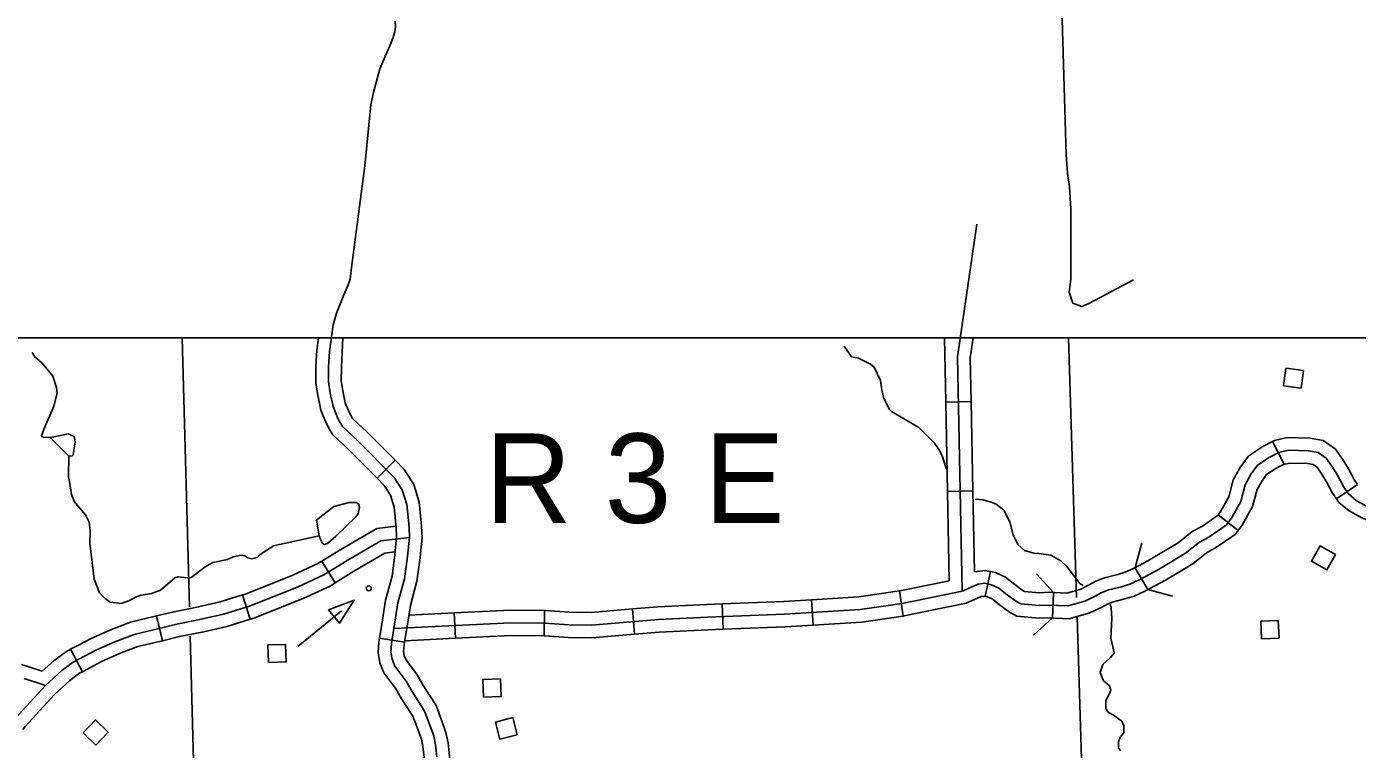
# Model space of a CAD drawing. Extents: x 1671357 to 13005564, y 567358 to 14261451.
# Drawn here: x 12758295.81 to 12758310.69, y 14259908.23 to 14259916.31 of the extents above; entities that cross this region are included whole.
import ezdxf

# ---------------------------------------------------------------- set-up
doc = ezdxf.new("R2010")
doc.units = 0
for name, color, linetype in [('2', 7, 'Continuous'), ('31', 7, 'Continuous'), ('32', 7, 'Continuous'), ('35', 7, 'Continuous'), ('38', 7, 'Continuous'), ('5', 7, 'Continuous'), ('56', 7, 'Continuous'), ('60', 7, 'Continuous')]:
    doc.layers.add(name, color=color, linetype=linetype)

msp = doc.modelspace()

# ---------------------------------------------------------------- linework, layer by layer
at = {"layer": '2'}
msp.add_line((12758241.044, 14259912.829), (12758347.654, 14259912.829), dxfattribs=at)
at = {"layer": '31'}
for p, q in [((12758299.932, 14259911.459), (12758299.731, 14259911.259)), ((12758299.758, 14259909.471), (12758300.038, 14259909.427))]:
    msp.add_line(p, q, dxfattribs=at)
for points in [[(12758299.933, 14259916.369), (12758299.936, 14259916.308), (12758299.93, 14259916.255), (12758299.911, 14259916.187), (12758299.882, 14259916.112), (12758299.762, 14259915.838), (12758299.692, 14259915.571), (12758299.661, 14259915.433), (12758299.595, 14259914.752), (12758299.44, 14259913.584), (12758299.429, 14259913.485), (12758299.408, 14259913.421), (12758299.352, 14259913.292), (12758299.277, 14259913.105), (12758299.24, 14259912.974), (12758299.199, 14259912.674), (12758299.19, 14259912.506), (12758299.188, 14259912.337), (12758299.208, 14259912.21), (12758299.239, 14259912.061), (12758299.293, 14259911.928), (12758299.344, 14259911.838), (12758299.516, 14259911.677), (12758299.923, 14259911.267), (12758299.963, 14259911.205), (12758300.011, 14259911.129), (12758300.062, 14259910.963), (12758300.088, 14259910.713), (12758300.092, 14259910.597), (12758300.071, 14259910.383), (12758300.038, 14259910.135), (12758299.963, 14259909.866)], [(12758299.086, 14259912.099), (12758299.068, 14259912.184), (12758299.046, 14259912.327), (12758299.048, 14259912.511), (12758299.058, 14259912.687), (12758299.077, 14259912.829)], [(12758299.35, 14259912.829), (12758299.332, 14259912.501), (12758299.33, 14259912.347), (12758299.347, 14259912.236), (12758299.364, 14259912.158)], [(12758299.731, 14259911.259), (12758299.417, 14259911.575), (12758299.231, 14259911.749), (12758299.165, 14259911.866), (12758299.103, 14259912.019), (12758299.086, 14259912.099)], [(12758299.364, 14259912.158), (12758299.376, 14259912.103), (12758299.421, 14259911.989), (12758299.457, 14259911.927), (12758299.615, 14259911.779), (12758299.932, 14259911.459)], [(12758299.932, 14259911.459), (12758300.034, 14259911.356), (12758300.082, 14259911.282), (12758300.141, 14259911.189), (12758300.202, 14259910.992), (12758300.229, 14259910.723), (12758300.234, 14259910.593), (12758300.217, 14259910.418)], [(12758299.731, 14259911.259), (12758299.811, 14259911.177), (12758299.843, 14259911.129), (12758299.88, 14259911.069), (12758299.922, 14259910.935), (12758299.946, 14259910.703), (12758299.949, 14259910.602), (12758299.934, 14259910.446)], [(12758299.934, 14259910.446), (12758299.929, 14259910.4), (12758299.898, 14259910.163), (12758299.824, 14259909.896), (12758299.779, 14259909.601), (12758299.758, 14259909.471)], [(12758300.217, 14259910.418), (12758300.212, 14259910.367), (12758300.177, 14259910.107), (12758300.103, 14259909.836), (12758300.059, 14259909.557), (12758300.038, 14259909.427)], [(12758299.963, 14259909.866), (12758299.919, 14259909.579), (12758299.892, 14259909.41), (12758299.885, 14259909.315), (12758299.898, 14259909.234), (12758299.931, 14259909.155), (12758299.988, 14259909.08), (12758300.056, 14259908.989), (12758300.125, 14259908.865), (12758300.259, 14259908.661), (12758300.287, 14259908.587), (12758300.321, 14259908.497), (12758300.364, 14259908.377), (12758300.383, 14259908.279), (12758300.399, 14259908.143)], [(12758300.163, 14259908.513), (12758300.154, 14259908.537), (12758300.132, 14259908.597), (12758300.004, 14259908.791), (12758299.937, 14259908.911), (12758299.874, 14259908.994), (12758299.807, 14259909.084), (12758299.76, 14259909.194), (12758299.742, 14259909.309), (12758299.751, 14259909.427), (12758299.758, 14259909.471)], [(12758300.038, 14259909.427), (12758300.033, 14259909.394), (12758300.028, 14259909.321), (12758300.035, 14259909.273), (12758300.055, 14259909.227), (12758300.101, 14259909.165), (12758300.175, 14259909.067), (12758300.247, 14259908.939), (12758300.387, 14259908.726), (12758300.42, 14259908.637), (12758300.428, 14259908.614)], [(12758300.23, 14259907.591), (12758300.247, 14259907.801), (12758300.256, 14259907.942), (12758300.257, 14259908.135), (12758300.243, 14259908.257), (12758300.227, 14259908.339), (12758300.188, 14259908.448), (12758300.163, 14259908.513)], [(12758300.428, 14259908.614), (12758300.454, 14259908.546), (12758300.501, 14259908.415), (12758300.524, 14259908.301), (12758300.541, 14259908.15), (12758300.54, 14259907.933), (12758300.531, 14259907.78), (12758300.513, 14259907.568)]]:
    msp.add_lwpolyline(points, dxfattribs=at)
at = {"layer": '32'}
for p, q in [((12758306.086, 14259912.111), (12758306.37, 14259912.117)), ((12758309.737, 14259911.668), (12758309.868, 14259911.416)), ((12758310.685, 14259911.19), (12758310.451, 14259911.029)), ((12758306.105, 14259911.111), (12758306.389, 14259911.117)), ((12758309.128, 14259910.849), (12758309.353, 14259910.675)), ((12758299.114, 14259910.331), (12758299.264, 14259910.09)), ((12758306.586, 14259910.216), (12758306.527, 14259909.938)), ((12758308.2, 14259910.261), (12758308.345, 14259910.014)), ((12758305.568, 14259909.998), (12758305.609, 14259909.717)), ((12758307.29, 14259909.98), (12758307.277, 14259909.696)), ((12758298.229, 14259909.954), (12758298.313, 14259909.682)), ((12758303.589, 14259909.854), (12758303.6, 14259909.57)), ((12758304.585, 14259909.9), (12758304.603, 14259909.616)), ((12758297.267, 14259909.719), (12758297.334, 14259909.442)), ((12758300.592, 14259909.754), (12758300.606, 14259909.47)), ((12758301.6, 14259909.781), (12758301.598, 14259909.497)), ((12758302.585, 14259909.797), (12758302.608, 14259909.513)), ((12758296.306, 14259909.346), (12758296.438, 14259909.095))]:
    msp.add_line(p, q, dxfattribs=at)
for points in [[(12758308.184, 14259913.478), (12758307.683, 14259913.212), (12758307.605, 14259913.18), (12758307.505, 14259913.216), (12758307.465, 14259913.34), (12758307.484, 14259913.483), (12758307.485, 14259914.271), (12758307.469, 14259914.518), (12758307.447, 14259914.671), (12758307.431, 14259914.879), (12758307.374, 14259916.774), (12758307.332, 14259916.877), (12758306.507, 14259917.42), (12758305.278, 14259917.327)], [(12758306.434, 14259914.098), (12758306.218, 14259912.615), (12758306.269, 14259909.996)], [(12758306.072, 14259912.829), (12758306.086, 14259912.111)], [(12758306.393, 14259912.829), (12758306.36, 14259912.606), (12758306.37, 14259912.117)], [(12758306.086, 14259912.111), (12758306.105, 14259911.111)], [(12758306.37, 14259912.117), (12758306.389, 14259911.117)], [(12758309.737, 14259911.668), (12758309.629, 14259911.612), (12758309.471, 14259911.509), (12758309.38, 14259911.385), (12758309.298, 14259911.239), (12758309.249, 14259911.051), (12758309.159, 14259910.889), (12758309.128, 14259910.849)], [(12758310.685, 14259911.19), (12758310.652, 14259911.238), (12758310.587, 14259911.363), (12758310.518, 14259911.472), (12758310.441, 14259911.583), (12758310.302, 14259911.681), (12758310.156, 14259911.707), (12758309.899, 14259911.713), (12758309.759, 14259911.679), (12758309.737, 14259911.668)], [(12758310.793, 14259910.944), (12758310.673, 14259911.011), (12758310.584, 14259911.086), (12758310.53, 14259911.165), (12758310.464, 14259911.292), (12758310.399, 14259911.393), (12758310.338, 14259911.482), (12758310.247, 14259911.546), (12758310.141, 14259911.565), (12758309.914, 14259911.571), (12758309.809, 14259911.545), (12758309.701, 14259911.49), (12758309.57, 14259911.404), (12758309.5, 14259911.308), (12758309.431, 14259911.186), (12758309.382, 14259910.998), (12758309.278, 14259910.811), (12758309.219, 14259910.734), (12758309.027, 14259910.601), (12758308.92, 14259910.545), (12758308.766, 14259910.419), (12758308.47, 14259910.243), (12758308.255, 14259910.126), (12758308.141, 14259910.074), (12758308.048, 14259910.045), (12758307.903, 14259910.009), (12758307.823, 14259909.977), (12758307.756, 14259909.94), (12758307.639, 14259909.882), (12758307.45, 14259909.83), (12758307.235, 14259909.84), (12758307.131, 14259909.834), (12758306.924, 14259909.854), (12758306.875, 14259909.88), (12758306.772, 14259909.956), (12758306.679, 14259910.03), (12758306.596, 14259910.068), (12758306.522, 14259910.084), (12758306.446, 14259910.073), (12758306.383, 14259910.048), (12758306.32, 14259910.019), (12758306.269, 14259909.996), (12758305.597, 14259909.859)], [(12758309.868, 14259911.416), (12758309.773, 14259911.367), (12758309.669, 14259911.3), (12758309.62, 14259911.231), (12758309.564, 14259911.132), (12758309.515, 14259910.944), (12758309.397, 14259910.732), (12758309.353, 14259910.675)], [(12758310.451, 14259911.029), (12758310.408, 14259911.092), (12758310.341, 14259911.22), (12758310.28, 14259911.315), (12758310.236, 14259911.381), (12758310.191, 14259911.412), (12758310.127, 14259911.423), (12758309.929, 14259911.428), (12758309.859, 14259911.411), (12758309.868, 14259911.416)], [(12758306.105, 14259911.111), (12758306.125, 14259910.111)], [(12758306.389, 14259911.117), (12758306.407, 14259910.211)], [(12758311.208, 14259910.407), (12758311.043, 14259910.632), (12758310.99, 14259910.692), (12758310.936, 14259910.735), (12758310.837, 14259910.776), (12758310.734, 14259910.815), (12758310.592, 14259910.894), (12758310.478, 14259910.989), (12758310.451, 14259911.029)], [(12758299.945, 14259910.722), (12758299.727, 14259910.695), (12758299.325, 14259910.462), (12758299.114, 14259910.331)], [(12758309.128, 14259910.849), (12758309.12, 14259910.838), (12758308.954, 14259910.723), (12758308.841, 14259910.664), (12758308.684, 14259910.536), (12758308.399, 14259910.367), (12758308.343, 14259910.336)], [(12758300.092, 14259910.597), (12758299.773, 14259910.557), (12758299.398, 14259910.34), (12758299.137, 14259910.179), (12758298.848, 14259910.044), (12758298.307, 14259909.829), (12758298.016, 14259909.739), (12758297.766, 14259909.681), (12758297.494, 14259909.627), (12758297.017, 14259909.512), (12758296.799, 14259909.428), (12758296.589, 14259909.336), (12758296.461, 14259909.268), (12758296.335, 14259909.201), (12758296.208, 14259909.107), (12758296.024, 14259908.939), (12758295.686, 14259908.571)], [(12758309.353, 14259910.675), (12758309.318, 14259910.63), (12758309.101, 14259910.479), (12758308.998, 14259910.426), (12758308.847, 14259910.302), (12758308.54, 14259910.12), (12758308.479, 14259910.086)], [(12758299.933, 14259910.434), (12758299.819, 14259910.42), (12758299.471, 14259910.218), (12758299.264, 14259910.09)], [(12758299.114, 14259910.331), (12758299.07, 14259910.304), (12758298.791, 14259910.175), (12758298.26, 14259909.963), (12758298.229, 14259909.954)], [(12758308.343, 14259910.336), (12758308.191, 14259910.253), (12758308.091, 14259910.207), (12758308.01, 14259910.182), (12758307.859, 14259910.144), (12758307.762, 14259910.106), (12758307.69, 14259910.066), (12758307.589, 14259910.015), (12758307.45, 14259909.978)], [(12758306.586, 14259910.216), (12758306.526, 14259910.228), (12758306.407, 14259910.211)], [(12758307.45, 14259909.978), (12758307.434, 14259909.973), (12758307.234, 14259909.983), (12758307.134, 14259909.977), (12758306.966, 14259909.993), (12758306.951, 14259910.001), (12758306.858, 14259910.069), (12758306.755, 14259910.152), (12758306.641, 14259910.204), (12758306.586, 14259910.216)], [(12758299.264, 14259910.09), (12758299.205, 14259910.053), (12758298.904, 14259909.914), (12758298.355, 14259909.695), (12758298.313, 14259909.682)], [(12758305.568, 14259909.998), (12758305.115, 14259909.933), (12758304.585, 14259909.9)], [(12758306.125, 14259910.111), (12758305.572, 14259909.999), (12758305.568, 14259909.998)], [(12758308.479, 14259910.086), (12758308.318, 14259909.999), (12758308.192, 14259909.941), (12758308.086, 14259909.908), (12758307.947, 14259909.873), (12758307.884, 14259909.848), (12758307.822, 14259909.814), (12758307.69, 14259909.749), (12758307.525, 14259909.704)], [(12758298.229, 14259909.954), (12758297.978, 14259909.876), (12758297.736, 14259909.82), (12758297.463, 14259909.766), (12758297.267, 14259909.719)], [(12758305.597, 14259909.859), (12758305.13, 14259909.792), (12758304.283, 14259909.738), (12758303.422, 14259909.705), (12758302.876, 14259909.678), (12758302.126, 14259909.616), (12758301.872, 14259909.62), (12758301.606, 14259909.639), (12758301.225, 14259909.642), (12758299.919, 14259909.579)], [(12758303.589, 14259909.854), (12758303.416, 14259909.847), (12758302.867, 14259909.82), (12758302.585, 14259909.797)], [(12758304.585, 14259909.9), (12758304.276, 14259909.88), (12758303.589, 14259909.854)], [(12758306.527, 14259909.938), (12758306.517, 14259909.94), (12758306.483, 14259909.935), (12758306.439, 14259909.918), (12758306.379, 14259909.89), (12758306.314, 14259909.86), (12758305.621, 14259909.719), (12758305.609, 14259909.717)], [(12758307.525, 14259909.704), (12758307.466, 14259909.687), (12758307.236, 14259909.698), (12758307.129, 14259909.692), (12758306.881, 14259909.715), (12758306.799, 14259909.76), (12758306.685, 14259909.843), (12758306.604, 14259909.908), (12758306.551, 14259909.933), (12758306.527, 14259909.938)], [(12758297.267, 14259909.719), (12758296.975, 14259909.648), (12758296.745, 14259909.56), (12758296.527, 14259909.464), (12758296.395, 14259909.393), (12758296.306, 14259909.346)], [(12758298.313, 14259909.682), (12758298.053, 14259909.602), (12758297.796, 14259909.542), (12758297.524, 14259909.489), (12758297.334, 14259909.442)], [(12758300.592, 14259909.754), (12758300.086, 14259909.729)], [(12758301.6, 14259909.781), (12758301.222, 14259909.784), (12758300.592, 14259909.754)], [(12758302.585, 14259909.797), (12758302.122, 14259909.758), (12758301.879, 14259909.762), (12758301.612, 14259909.781), (12758301.6, 14259909.781)], [(12758305.609, 14259909.717), (12758305.144, 14259909.65), (12758304.603, 14259909.616)], [(12758303.6, 14259909.57), (12758303.429, 14259909.563), (12758302.885, 14259909.537), (12758302.608, 14259909.513)], [(12758304.603, 14259909.616), (12758304.29, 14259909.596), (12758303.6, 14259909.57)], [(12758297.334, 14259909.442), (12758297.059, 14259909.376), (12758296.853, 14259909.297), (12758296.651, 14259909.208), (12758296.528, 14259909.142), (12758296.438, 14259909.095)], [(12758300.606, 14259909.47), (12758300.042, 14259909.442)], [(12758301.598, 14259909.497), (12758301.228, 14259909.5), (12758300.606, 14259909.47)], [(12758302.608, 14259909.513), (12758302.131, 14259909.474), (12758301.866, 14259909.478), (12758301.601, 14259909.497), (12758301.598, 14259909.497)], [(12758296.306, 14259909.346), (12758296.259, 14259909.322), (12758296.118, 14259909.216), (12758295.99, 14259909.1)], [(12758295.758, 14259909.175), (12758295.829, 14259909.154), (12758295.99, 14259909.1)], [(12758296.438, 14259909.095), (12758296.411, 14259909.081), (12758296.299, 14259908.997), (12758296.124, 14259908.838), (12758295.797, 14259908.482), (12758295.773, 14259908.448)], [(12758295.786, 14259909.018), (12758296.024, 14259908.939)]]:
    msp.add_lwpolyline(points, dxfattribs=at)
at = {"layer": '35'}
for points in [[(12758295.875, 14259912.663), (12758295.904, 14259912.62), (12758295.99, 14259912.545), (12758296.106, 14259912.4), (12758296.149, 14259912.273), (12758296.157, 14259912.21), (12758296.118, 14259912.066), (12758296.002, 14259911.796), (12758295.98, 14259911.73), (12758296.009, 14259911.714), (12758296.1, 14259911.719)], [(12758304.951, 14259912.734), (12758305.034, 14259912.617), (12758305.112, 14259912.6), (12758305.245, 14259912.533), (12758305.286, 14259912.5), (12758305.356, 14259912.35), (12758305.371, 14259912.246), (12758305.393, 14259912.15), (12758305.456, 14259912.028), (12758305.48, 14259912.006)], [(12758305.48, 14259912.006), (12758305.785, 14259911.824), (12758305.959, 14259911.649), (12758306.015, 14259911.571), (12758306.051, 14259911.499), (12758306.09, 14259911.366), (12758306.096, 14259911.353)], [(12758296.1, 14259911.719), (12758296.28, 14259911.756), (12758296.346, 14259911.726), (12758296.357, 14259911.667), (12758296.336, 14259911.52), (12758296.323, 14259911.51), (12758296.285, 14259911.505), (12758296.091, 14259911.7), (12758296.081, 14259911.717)], [(12758296.285, 14259911.505), (12758296.282, 14259911.275), (12758296.295, 14259911.222), (12758296.317, 14259911.078), (12758296.35, 14259910.996), (12758296.382, 14259910.953), (12758296.471, 14259910.851), (12758296.514, 14259910.767), (12758296.526, 14259910.678), (12758296.52, 14259910.534), (12758296.57, 14259910.128), (12758296.628, 14259909.976), (12758296.693, 14259909.914)], [(12758306.419, 14259911.023), (12758306.503, 14259911.016), (12758306.603, 14259910.988), (12758306.649, 14259910.967), (12758306.734, 14259910.902), (12758306.802, 14259910.77), (12758306.838, 14259910.624), (12758306.892, 14259910.518), (12758306.967, 14259910.452), (12758307.069, 14259910.419), (12758307.124, 14259910.415), (12758307.261, 14259910.4), (12758307.372, 14259910.336), (12758307.437, 14259910.272), (12758307.585, 14259910.083), (12758307.62, 14259910.06)], [(12758299.085, 14259910.615), (12758299.054, 14259910.791), (12758299.246, 14259910.941), (12758299.42, 14259910.989), (12758299.496, 14259910.987), (12758299.522, 14259910.971), (12758299.536, 14259910.932), (12758299.518, 14259910.861), (12758299.489, 14259910.822), (12758299.271, 14259910.611), (12758299.177, 14259910.527), (12758299.143, 14259910.519), (12758299.118, 14259910.533), (12758299.085, 14259910.615)], [(12758296.693, 14259909.914), (12758296.749, 14259909.874), (12758296.871, 14259909.857), (12758296.963, 14259909.891), (12758297.039, 14259909.933), (12758297.095, 14259909.951), (12758297.21, 14259909.97), (12758297.309, 14259910.008), (12758297.471, 14259910.143), (12758297.509, 14259910.155), (12758297.608, 14259910.144), (12758297.655, 14259910.149), (12758297.821, 14259910.277), (12758297.894, 14259910.315), (12758298.059, 14259910.35), (12758298.121, 14259910.38), (12758298.207, 14259910.397), (12758298.255, 14259910.392), (12758298.286, 14259910.367), (12758298.332, 14259910.357), (12758298.39, 14259910.371), (12758298.425, 14259910.404), (12758298.575, 14259910.504), (12758299.085, 14259910.615)], [(12758307.923, 14259909.846), (12758307.934, 14259909.813), (12758307.941, 14259909.689), (12758307.932, 14259909.471), (12758307.957, 14259909.358), (12758307.967, 14259909.301), (12758307.924, 14259909.25), (12758307.84, 14259909.176), (12758307.813, 14259909.086), (12758307.849, 14259908.994), (12758307.914, 14259908.936), (12758307.929, 14259908.889), (12758307.923, 14259908.87), (12758307.874, 14259908.769), (12758307.874, 14259908.682), (12758307.902, 14259908.643), (12758307.97, 14259908.6), (12758308.052, 14259908.543), (12758308.077, 14259908.489), (12758308.075, 14259908.411), (12758308.033, 14259908.362), (12758308.016, 14259908.31), (12758308.015, 14259908.241), (12758308.041, 14259908.21)]]:
    msp.add_lwpolyline(points, dxfattribs=at)
at = {"layer": '38'}
for p, q in [((12758308.275, 14259910.138), (12758308.275, 14259910.138)), ((12758307.284, 14259909.838), (12758307.284, 14259909.838))]:
    msp.add_line(p, q, dxfattribs=at)
for points in [[(12758308.278, 14259910.535), (12758308.204, 14259910.261)], [(12758307.29, 14259909.98), (12758307.099, 14259910.19)], [(12758308.345, 14259910.014), (12758308.62, 14259909.94)], [(12758307.067, 14259909.505), (12758307.277, 14259909.696)]]:
    msp.add_lwpolyline(points, dxfattribs=at)
at = {"layer": '5'}
for points in [[(12758297.634, 14259909.82), (12758297.554, 14259912.829)], [(12758307.459, 14259912.829), (12758307.546, 14259909.925)], [(12758307.553, 14259909.707), (12758307.627, 14259907.258), (12758307.77, 14259902.353)], [(12758297.803, 14259903.537), (12758297.714, 14259906.841), (12758297.643, 14259909.491)]]:
    msp.add_lwpolyline(points, dxfattribs=at)
at = {"layer": '56'}
msp.add_line((12758298.845, 14259909.378), (12758299.333, 14259909.774), dxfattribs=at)
for points in [[(12758309.861, 14259912.292), (12758309.887, 14259912.488), (12758310.083, 14259912.462), (12758310.057, 14259912.266)], [(12758310.441, 14259910.405), (12758310.345, 14259910.233), (12758310.172, 14259910.33), (12758310.269, 14259910.502)], [(12758299.19, 14259909.787), (12758299.311, 14259909.637), (12758299.476, 14259909.894)], [(12758309.613, 14259909.462), (12758309.605, 14259909.659), (12758309.802, 14259909.667), (12758309.811, 14259909.47)], [(12758298.517, 14259909.197), (12758298.511, 14259909.394), (12758298.708, 14259909.401), (12758298.715, 14259909.204)], [(12758300.921, 14259908.809), (12758300.912, 14259909.006), (12758301.11, 14259909.015), (12758301.118, 14259908.818)], [(12758296.59, 14259908.275), (12758296.448, 14259908.412), (12758296.585, 14259908.555), (12758296.727, 14259908.418)], [(12758301.104, 14259908.341), (12758301.055, 14259908.532), (12758301.247, 14259908.581), (12758301.296, 14259908.39)]]:
    msp.add_lwpolyline(points, close=True, dxfattribs=at)
msp.add_circle((12758299.639, 14259910.028), 0.0284, dxfattribs=at)

# ---------------------------------------------------------------- texts
at = {"layer": '60'}
msp.add_text('R 3 E', height=1, dxfattribs=at).set_placement((12758300.939, 14259910.759))

doc.saveas('drawing.dxf')
